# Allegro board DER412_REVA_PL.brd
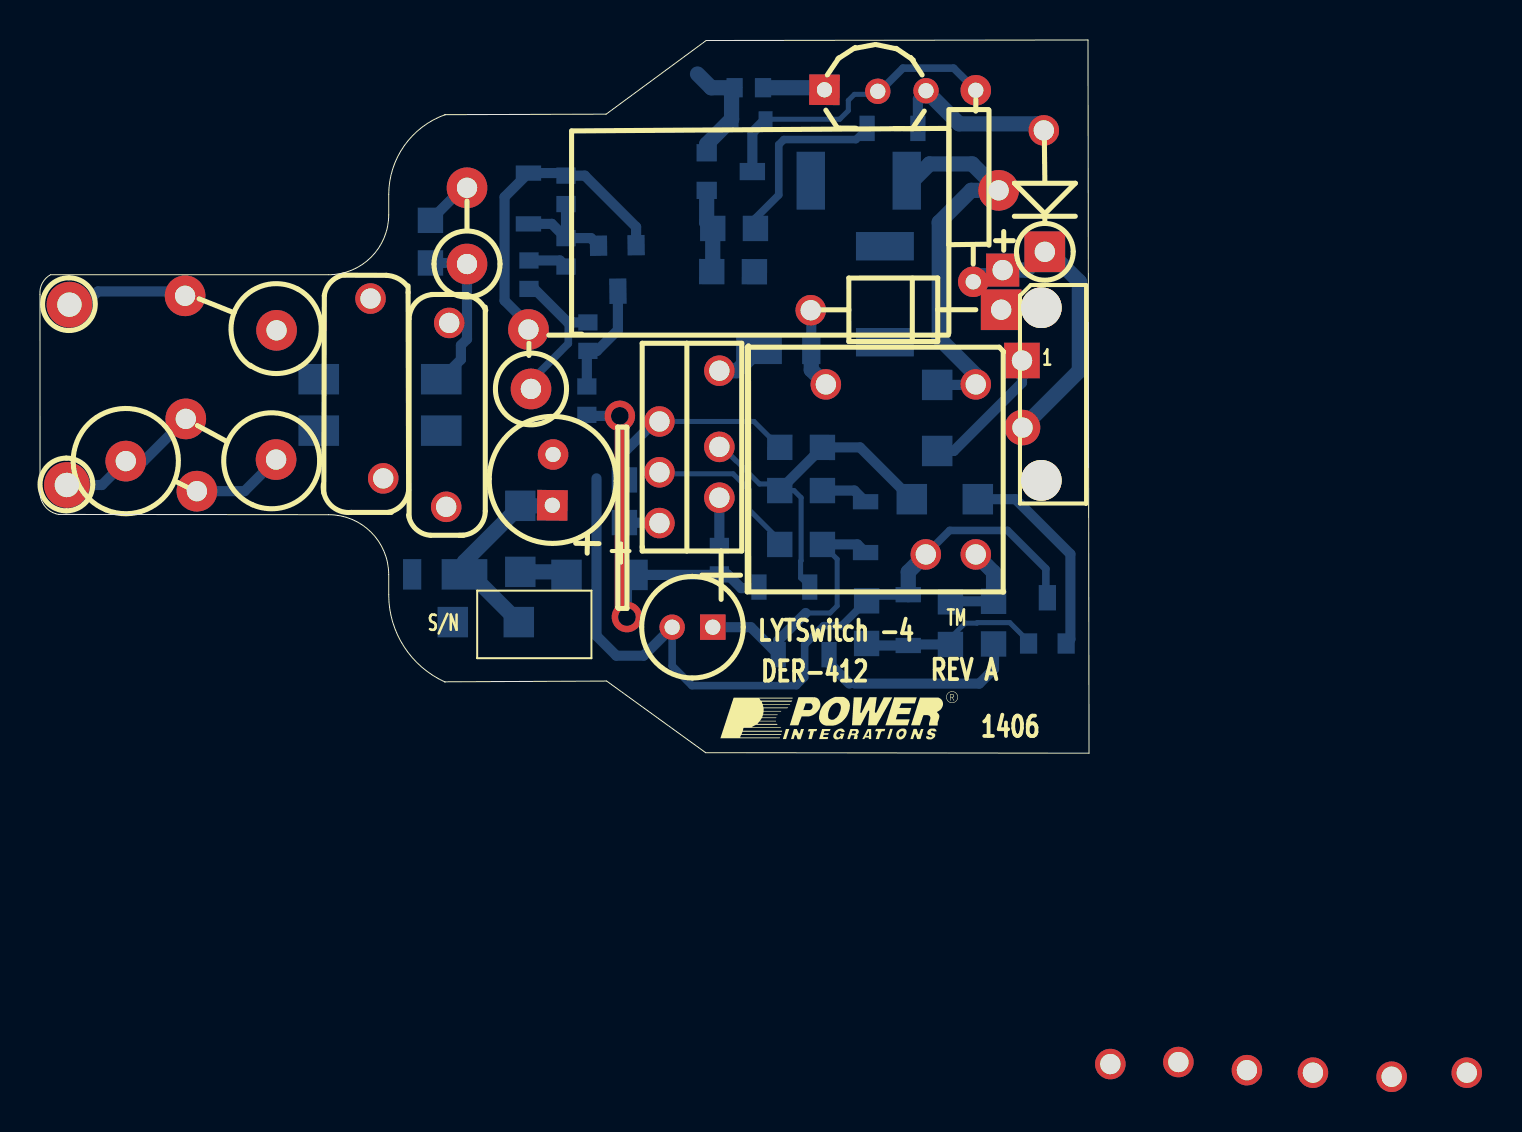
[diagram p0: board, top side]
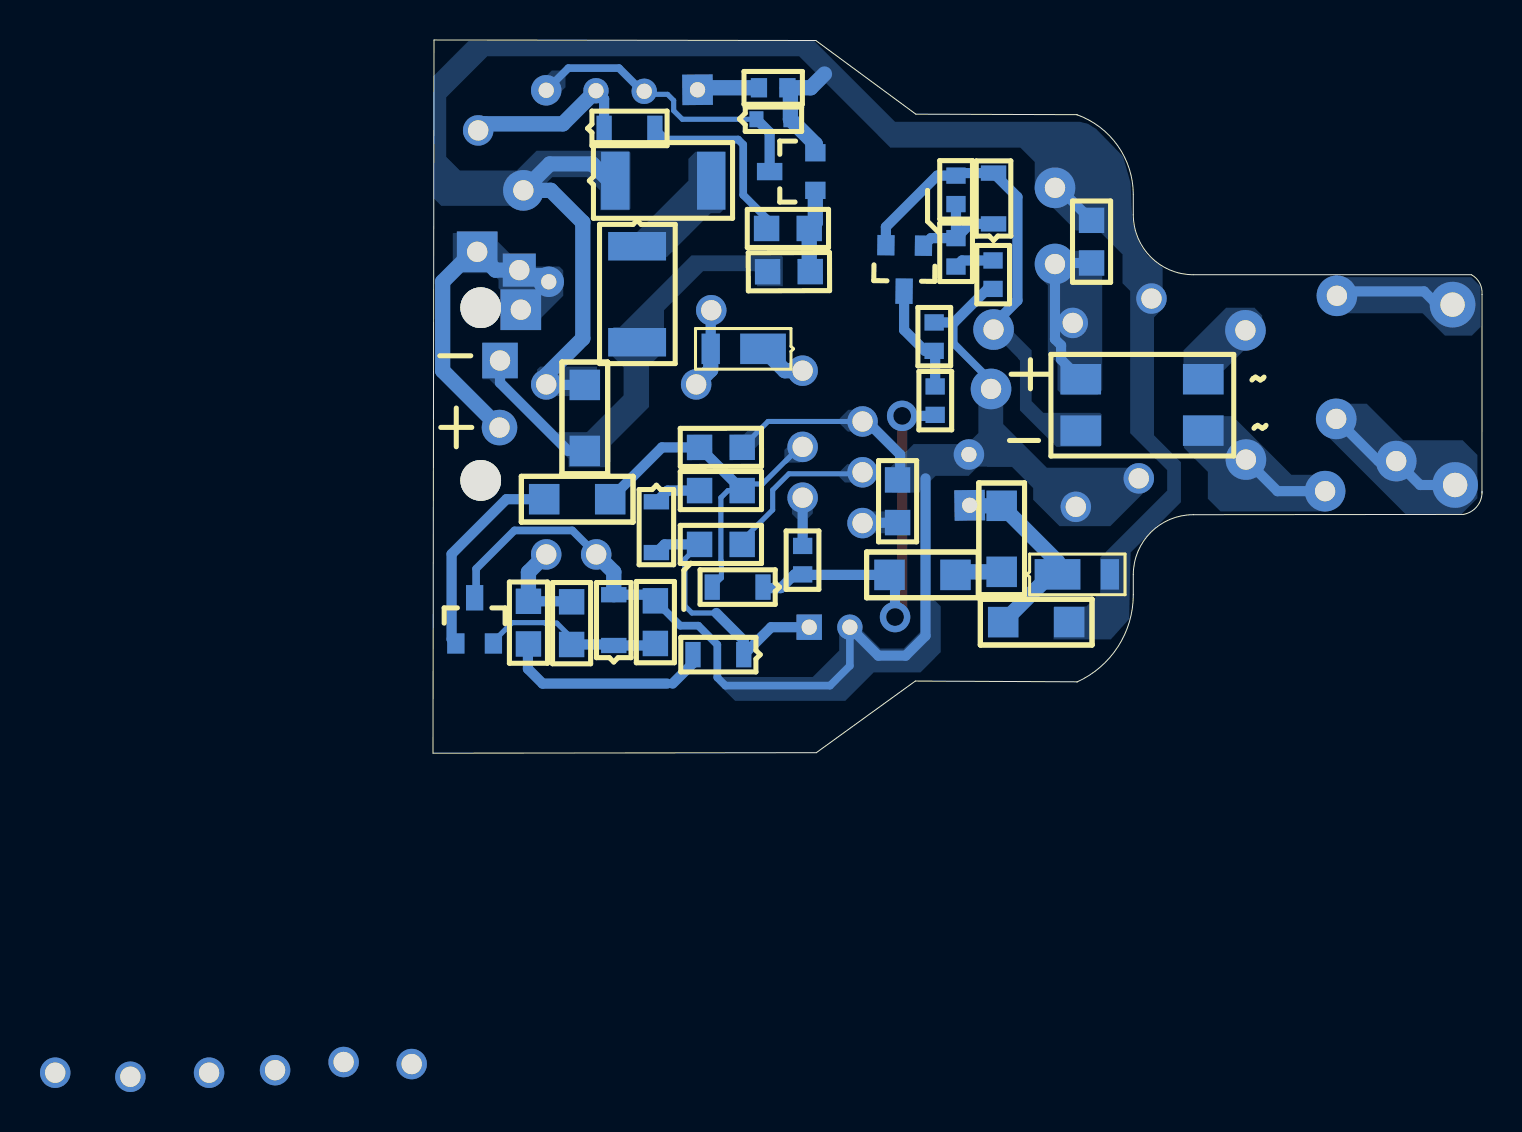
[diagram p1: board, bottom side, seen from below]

Outline 52.48 x 35.66 mm; copper layers: TOP, BOTTOM. Coordinates in mm from the lower left corner of the outline.
Outline path: 0,13 0,22.94 arc(0.12,23.51) 0.53,23.93 14.45,23.92 arc(16.57,24.8) 17.44,26.92 17.44,27.92 arc(18.22,30.37) 20.27,31.93 ; 0,13.08 arc(0.26,12.33) 0.94,11.94 14.45,11.93 arc(16.57,11.05) 17.44,8.93 17.44,7.92 arc(18.21,5.32) 20.27,3.56 ; 20.27,31.93 20.24,31.92 ; 20.27,31.93 28.32,31.95 33.32,35.64 52.43,35.66 52.48,0 33.3,0.03 28.35,3.61 20.24,3.57

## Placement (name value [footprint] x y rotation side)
BR1  B10S-G  [PISMSOIC4]  13.94 16.13 90 bottom
C1  10 nF  [PINPCAPRAD500X200400030]  20.29 21.95 270 top
C3  220 nF  [PI_NP_CAP_RAD470X220LS400D40]  16.54 23.09 270 top
C4  2.2 uF  [PIPOLCAPCYLD250LS100030]  25.63 12.4 89.1 top
C5  100 uF  [PIPOLCAPCYLD400LS200040]  48.69 23.5 90 top
C6  4.7 uF  [PIPOLCAPCLYD200LS80030]  33.66 6.3 180 top
C7  4.7 uF  [PISMC0805]  39.14 15.29 179.9 bottom
C8  680 pF  [PISMC0603]  27.41 20.12 90 bottom
C9  100 pF  [PISMC0603]  24.46 23.22 90 bottom
D2  DFLR1600-7  [PISMDDFLR120012]  21.26 8.94 0 bottom
D3  STTH1R06RL  [PIDV200X110X040DO41#2]  48.08 22.17 180 top
D4  BAV21WS-7-F  [PISMSOD323]  36.93 4.93 0 bottom
D5  DFLU1200-7  [PISMDDFLR120012]  35.94 20.22 180 bottom
D6  BAV16WS-7-F  [PISMSOD323]  41.3 12.57 270 bottom
D7  BAV16WS-7-F  [PISMSOD323]  43.43 5.38 90 bottom
D8  BAV16WS-7-F  [PISMSOD323]  24.43 26.47 90 bottom
D9  BAV16WS-7-F  [PISMSOD323]  35.97 8.31 0 bottom
D10  DL4003  [PISMDMLL4112]  43.36 28.63 180 bottom
D11  DL4003  [PISMDMLL4112]  42.27 25.35 270 bottom
FR1  47  [PI_2W_VRES240LS200D040]  11.58 20.73 151.2 top
J5  CON2  [PI_CONN_LEE_LEDS]  49.07 19.74 0 top
L  PCB Terminal 22 AWG  [PI_HOLE_22AWG]  1.47 22.43 0 top
L1  4.7 mH  [PI12WVRESD180LS150D040]  21.36 24.46 90 top
N  PCB Terminal 22 AWG  [PI_HOLE_22AWG]  1.35 13.41 0 top
NOREF  -  []  0.94 11.94 90 top
NOREF#2  -  []  -225.4 -138.86 0 top
NOREF#3  -  []  34.04 0.69 0 top
NOREF#4  -  []  -147.58 60.15 0 top
NOREF#5  -  []  0 14.02 0 top
NOREF#6  -  []  52.48 0 90 top
Q1  MMBT3904  [PISMSOT23132]  29.82 25.4 0.7 bottom
Q4  2N7000  [PITO92R100]  39.24 33.17 359.5 top
Q5  MMBT3904  [PISMSOT23132]  33.35 30.02 90 bottom
R1  10 k  [PISMR0805]  19.53 24.51 90 bottom
R6  27  [PI1WRESD200LS725D040]  24.56 18.21 90.7 top
R8  510 k  [PISMR1206]  20.65 6.55 0 bottom
R9  1.50 M  [PISMR1206]  24.03 12.37 270 bottom
R10  1.50 M  [PISMR1206]  26.34 8.92 0 bottom
R13  82 k  [PISMR0603]  27.36 16.92 90 bottom
R14  137 k  [PISMR0805]  37.01 10.44 0 bottom
R15  24.9 k  [PISMR0805]  29.24 13.67 270 bottom
R16  6.2 k  [PISMR0805]  39.14 13.13 180 bottom
R17  20  [PISMR1206]  46.91 12.7 180 bottom
R18  62 k  [PISMR0805]  45.54 5.44 90 bottom
R20  100 k  [PISMR0603]  26.31 27.46 90 bottom
R21  10 k  [PISMR0603]  26.31 24.33 90 bottom
R22  191 k  [PISMR0603]  33.99 10.36 270 bottom
R24  200  [PI2WRESD200LS725D040#2]  4.29 14.61 338 top
R25  5.1 k  [PISMR0805]  41.35 7.62 270 bottom
R33  10  [PISMR0805]  47.7 7.59 270 bottom
R35  680  [PISMR0603]  36.17 33.27 180 bottom
R36  1 M  [PI14WRESD100LS400D030]  46.69 33.73 270 top
R37  1 k  [PISMR0805]  33.6 24.08 359.8 bottom
R38  130  [PISMR1206]  44.88 18.41 270 bottom
R39  10 k  [PISMR0805]  33.66 26.24 0 bottom
R40  200  [PI2WRESD200LS725D040]  11.81 14.68 156.3 top
T1  EE13  [PI_BOBBIN_EE13V_10P]  46.81 18.44 180 top
U1  LYT4322E  [PIICESIP76TH]  30.99 11.51 90 top
U2  LM431AIM3  [PISMSOT23123]  49.45 5.49 180 bottom
VR1  DZ2S062M0L  [PI_SM_D_SSMINI2P]  36.3 31.7 180 bottom
VR2  1N4761A  [PIDV200X110X040DO41]  50.27 25.07 90 top
VR3  BZX384-B56,115  [PISMSOD323]  43.92 31.24 180 bottom

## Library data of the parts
BR1 = DIODE BRIDGE_~~+-: alternate symbols: (pi_sm_soic4_slot); room: 1
C1 C3 C7-C9 = CAP NP
C4 = CAP POL: alternate symbols: (pipolcapcyld250ls100030h)
C5 = CAP POL: alternate symbols: (pipolcapcyld400ls200040800h)
C6 = CAP POL: alternate symbols: (pipolcapclyd200ls80030h)
D2 D4-D11 = DIODE
D3 = DIODE: alternate symbols: (pidax475x125040do41,pidax390x125040do41)
FR1 = R: alternate symbols: (PI_2W_RES240LS500D040,pi_2w_resd145ls455d040); tolerance: 5%
J5 = CON2
L N = TERM_1Pin
L1 = INDUCTOR
Q1 Q5 = NPN_BEC
Q4 = FET_N_SGD
R1 = R: room: 1
R6 = R: alternate symbols: (pi1wvresd120ls200d040,pi1wvresd120ls300d040,pi1wvresd200ls200d040,pi1wvresd200ls300d040,pi1wvresd200ls350d040)
R8-R10 R13-R18 R20-R22 R25 R33 R35 R37-R39 = R
R24 R40 = R: alternate symbols: (pi2wresd200ls900d040,pi2wvresd200ls300d040,pi2wvresd200ls400d040,pi2wresd200ls725d040)
R36 = R: alternate symbols: (pi14wvresd100ls200d030,pi14wresd100ls400d030,pi14wresd100ls500d030)
T1 = BEE13/10PINS/GENERIC
U1 = LNK40X_eSIP
U2 = TL431/SOT-23_CAR
VR1 VR3 = DIODE_ZENER
VR2 = DIODE_ZENER: alternate symbols: (pidax475x125040do41,pidv200x110x040do41wbead,pidax390x125040do41)

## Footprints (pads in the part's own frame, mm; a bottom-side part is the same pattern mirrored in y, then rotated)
PI1WRESD200LS725D040
  round 2.032 hole 1.016: 1(0,0) 2(2.973,0.09)
PI2WRESD200LS725D040
  round 2.032 hole 1.016: 1(0,0) 2(4.953,-0.051)
PI2WRESD200LS725D040#2
  round 2.032 hole 1.016: 1(0,0) 2(3.862,-0.059)
PI12WVRESD180LS150D040
  round 2.032 hole 1.016: 1(0,0) 2(3.81,0)
PI14WRESD100LS400D030
  round 1.524 hole 0.762: 1(0.584,0.127) 2(10.16,0)
PI_2W_VRES240LS200D040
  round 2.032 hole 1.016: 1(-0.02,-0.488) 2(4.822,0.207)
PI_BOBBIN_EE13V_10P
  round 1.524 hole 1.016: 1(0,0) 2(-16.866,34.417) 3(-20.803,34.62) 4(7.501,0) 5(-24.562,34.417) 6(-6.731,33.985) 7(-10.135,33.884) 8(-13.564,34.29) 9(2.499,8.501) 10(0,8.501)
PI_CONN_LEE_LEDS
  round 2.032 hole 2.032: (1.016,2.54) (1.016,-6.096)
  rect 1.778x1.778 hole 1.016: 1(0.051,-0.102)
  round 1.778 hole 1.016: 2(0.076,-3.454)
PI_HOLE_22AWG
  round 2.286 hole 1.219: 1(0,0)
PI_NP_CAP_RAD470X220LS400D40
  round 1.524 hole 1.016: 1(0.356,0) 2(9.347,0.635)
PI_SM_D_SSMINI2P
  rect 0.699x0.8 smd: 1(0,0) 2(1.7,0)
PIDV200X110X040DO41
  rect 2.032x2.032 hole 1.016: 1(0,0)
  round 1.524 hole 1.016: 2(6.071,0.051)
PIDV200X110X040DO41#2
  rect 2.032x2.032 hole 1.016: 1(0,0)
  round 1.524 hole 1.016: 2(9.525,0.022)
PIICESIP76TH
  round 1.524 hole 1.016: 1(0,0) 2(1.27,-2.997) 3(2.54,0) 4(3.81,-2.997) 5(5.08,0) 7(7.62,-2.997)
PINPCAPRAD500X200400030
  round 1.524 hole 1.016: 1(0.432,0.178) 2(9.627,0.025)
PIPOLCAPCLYD200LS80030
  rect 1.27x1.27 hole 0.762: 1(0,0)
  round 1.27 hole 0.762: 2(2.032,0)
PIPOLCAPCYLD250LS100030
  rect 1.524x1.524 hole 0.762: 1(0,0)
  round 1.524 hole 0.762: 2(2.54,0)
PIPOLCAPCYLD400LS200040
  rect 1.651x1.651 hole 1.016: 1(0.66,0.533)
  round 2.032 hole 1.016: 2(4.648,0.737)
PISMC0603
  rect 0.813x0.965 smd: 1(0,0) 2(1.422,0)
PISMC0805
  rect 1.27x1.27 smd: 1(0,0) 2(2.134,0)
PISMDDFLR120012
  rect 2.286x1.524 smd: 1(-0.025,0)
  rect 0.914x1.524 smd: 2(-2.642,0)
PISMDMLL4112
  rect 1.422x2.896 smd: 1(0,0) 2(4.801,0)
PISMR0603
  rect 0.813x0.965 smd: 1(0,0) 2(1.422,0)
PISMR0805
  rect 1.27x1.27 smd: 1(0,0) 2(2.134,0)
PISMR1206
  rect 1.524x1.524 smd: 1(0,0) 2(3.302,0)
PISMSOD323
  rect 0.762x1.27 smd: 1(0,0) 2(2.54,0)
PISMSOIC4
  rect 1.524x2.032 smd: 1(0,0) 2(2.57,0) 3(2.57,6.129) 4(0,6.129)
PISMSOT23123
  rect 0.864x1.016 smd: 1(-1.88,0) 3(0,0)
  rect 0.864x1.27 smd: 2(-0.94,2.286)
PISMSOT23132
  rect 0.864x1.016 smd: 1(-1.88,0) 2(0,0)
  rect 0.864x1.27 smd: 3(-0.94,2.286)
PITO92R100
  rect 1.524x1.524 hole 0.762: 1(0,0)
  round 1.27 hole 0.762: 2(2.667,-0.051) 3(5.08,0)

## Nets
N1678526: C1.2 C3.2 C4.2 C6.2 C7.2 C8.2 C9.1 D7.2 R6.1 R15.1 R25.1 T1.9 U1.5(S) U2.2(A)
N2200496: C4.1 D2.1 R8.2 R9.1
N2229506: BR1.4 D8.2 Q1.2(EMITTER) R6.2 R20.2
N2302506: FR1.2 L.1
N2491459: C7.1 D9.2 R16.2 R17.2 U1.4(BP)
N2492720: D5.1 U1.7(D)
N2492766: R15.2 U1.1(R)
N2493445: C3.1 C5.2 D2.2 D10.1 L1.2 Q5.2(EMITTER) R1.2 R8.1 R35.2 R38.1 T1.1 VR1.2
N2532048: R14.1 U1.3(FB)
N2536376: BR1.1 R24.2 R40.1
N2538393: BR1.3 C1.1 L1.1 R1.1
N3672068: C5.1 D3.1 J5.2 R36.2 VR2.1
N3711440: D3.2 D5.2 T1.4
N3740281: R22.1 U1.2(V)
N3830550: C6.1 D4.1 D6.2 R14.2
N3837669: R9.2 R10.1
N3895372: C8.1 Q1.3(COLLECTOR) R13.2
N3895502: D8.1 Q1.1(BASE) R20.1 R21.2
N3896990: D9.1 R10.2 R13.1 R22.2
N3918631: D7.1 R18.1 R25.2 U2.3(VREF)
N3918661: R17.1 U2.1(C)
N3918954: R18.2 R33.1 T1.10
N3939020: D6.1 R16.1
N3945438: T1.3
N3949879: D4.2 R33.2
N3952070: BR1.2 FR1.1
N3964753: Q4.2(G) Q5.3(COLLECTOR) R36.1 VR1.1
N3964758: Q4.1(S) R35.1
N3964791: Q4.3(D) VR2.2 VR3.1
N3965046: D11.2 J5.1 R37.2 R38.2
N3965058: Q5.1(BASE) R37.1 R39.1
N3965494: R39.2 VR3.2
N3967550: N.1 R24.1 R40.2
N38954281: C9.2 R21.1
N39661570: D10.2 D11.1

Pads without a net: T1 2 5 6 7 8

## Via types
v1: diameter 1.524, hole 0.889, TOP to BOTTOM, 2 vias

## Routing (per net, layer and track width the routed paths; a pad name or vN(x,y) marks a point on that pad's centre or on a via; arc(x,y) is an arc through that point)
N1678526: length 59.4
  BOTTOM w0.254: C7.2 35.72,16.59 U1.5
  BOTTOM w0.381: 26.41,21.54 26.43,21.52 26.43,20.49 24.56,18.62 R6.1 ; R25.1 40.11,6.38 39.2,6.38 38.25,5.42 38.25,3.78 37.85,3.38 32.61,3.38 31.62,4.37 C6.2 ; R15.1 28.93,13.64 ; U2.2 50.32,7.85 50.32,9.22 48.4,11.14 45.5,11.14 44.31,9.95 T1.9
  BOTTOM w0.508: D7.2 41.66,7.92 R25.1 ; C8.2 26.41,21.54 24.73,23.22 C9.1 ; U1.5 30.76,16.59 29.11,14.94 29.11,13.67 R15.1 ; C6.2 30.2,4.88 28.83,4.88 27.84,5.87 27.84,13.74
  BOTTOM w0.762: T1.9 43.43,9.06 D7.2
N2200496: length 9.9
  BOTTOM w0.762: R8.2 21.56,8.94 D2.1 21.23,9.58 R9.1 25.6,12.37 C4.1
N2229506: length 16.3
  BOTTOM w0.508: Q1.2 29.82,26.31 27.25,28.88 R20.2 26.19,29.01 D8.2 23.24,27.81 23.24,22.63 24.64,21.23
N2302506: length 6.1
  BOTTOM w0.508: L.1 2.24,22.43 2.9,23.09 7.04,23.09 FR1.2
N2491459: length 19.4
  BOTTOM w0.254: 34.11,15.32 34.82,14.61 ; 34.11,15.32 34.14,15.32 35.99,13.46 36.68,13.46 R16.2 37.72,13.13 38.07,12.78 38.07,9.63 38.05,9.6 38.05,8.76 D9.2 ; 34.11,15.32 U1.4
  BOTTOM w0.508: R17.2 41.02,15.29 C7.1 37.01,13.16 R16.2
N2492720: length 2.4
  BOTTOM w0.762: D5.1 34.87,19.13 U1.7
N2492766: length 1.8
  BOTTOM w0.508: R15.2 U1.1
N2493445: length 29.2
  BOTTOM w0.508: R1.2 21.16,28.27 L1.2 ; T1.1 46.79,18.41 R38.1
  BOTTOM w0.762: D10.1 43.66,28.63 44.5,29.46 46.63,29.46 C5.2 ; 47.8,27.99 C5.2 ; C5.2 46.58,28.14 44.98,26.54 44.98,20.74 46.81,18.91 T1.1 ; C5.2 47.96,28.68 ; Q5.2 33.35,30.45 VR1.2 34.6,33.12 R35.2 33.58,33.27 32.89,33.96
N2532048: length 8.3
  BOTTOM w0.254: 30.99,14.17 U1.3 31.06,13.97 34.67,13.97 35.48,13.16 35.48,12.17 37.01,10.64 R14.1
N2536376: length 4.6
  BOTTOM w0.508: R40.1 10.23,13.1 R24.2
N2538393: length 8.1
  BOTTOM w0.508: BR1.3 21.06,19.68 21.06,20.4 21.36,20.7 L1.1 21.31,24.51 R1.1
N3672068: length 16.2
  BOTTOM w0.508: 47.88,23.88 47.75,23.75 47.06,23.75 46.93,23.62 46.75,23.62
  BOTTOM w0.762: J5.2 51.99,19.13 51.99,23.57 50.5,25.07 VR2.1 49.35,24.16 C5.1 47.88,23.88 47.01,23.88 46.75,23.62
N3711440: length 4
  BOTTOM w0.508: D5.2 38.58,22.12 D3.2
  BOTTOM w0.762: D5.2 38.58,19.17 T1.4
N3740281: length 2.4
  BOTTOM w0.508: R22.1 U1.2
N3830550: length 13.9
  BOTTOM w0.254: 38.3,7.01 39.52,7.01 39.88,7.37 39.88,9.7 R14.2
  BOTTOM w0.508: 38.3,7.01 36.93,5.64 D4.1 35.56,6.3 C6.1 ; 41.3,10.03 40.89,10.44 R14.2
N3837669: length 2.4
  BOTTOM w0.762: R10.1 26.19,9.07 R9.2
N3895372: length 5.7
  BOTTOM w0.508: R13.2 27.36,20.07 C8.1 27.86,20.12 28.91,21.16 Q1.3
N3895502: length 5.7
  BOTTOM w0.508: R20.1 R21.2 ; R21.2 25.6,26.47 D8.1 ; R21.2 27.56,25.76 Q1.1
N3896990: length 20.7
  TOP w0.508: v1(29.36,6.81) 29.01,7.16 v1(29.01,16.87)
  BOTTOM w0.508: v1(29.01,16.87) 27.41,16.87 R13.1 ; v1(29.36,6.81) 29.36,8.64 R10.2 33.96,8.92 R22.2 34.39,8.94 35.08,8.26 35.92,8.26 D9.1
N3918631: length 9.3
  BOTTOM w0.254: R18.1 45.54,5.77 46.28,6.5 46.86,6.5 46.89,6.53 48.52,6.53 49.45,5.59 U2.3
  BOTTOM w0.508: R25.2 41.45,5.38 D7.1 43.48,5.44 R18.1
N3918661: length 10.3
  BOTTOM w0.508: U2.1 51.54,5.7 51.54,9.96 48.8,12.7 R17.1
N3918954: length 4.9
  BOTTOM w0.508: R18.2 45.57,7.59 R33.1
  BOTTOM w0.762: R33.1 47.7,9.05 T1.10
N3939020: length 2.4
  BOTTOM w0.508: D6.1 40.74,13.13 R16.1
N3949879: length 10.7
  BOTTOM w0.254: 40.49,3.48 40.77,3.48
  BOTTOM w0.508: 40.49,3.48 39.47,4.5 D4.2 ; R33.2 47.73,5.44 47.73,4.22 46.99,3.48 40.77,3.48
N3964753: length 15.2
  BOTTOM w0.254: Q4.2 41.76,32.94 40.74,32.94 40.44,32.64 40.44,32.13 40,31.7 VR1.1
  BOTTOM w0.381: R36.1 45.7,34.25 43.17,34.25 42.01,33.1 Q4.2
  BOTTOM w0.508: VR1.1 35.64,31.04 Q5.3
N3964758: length 3.1
  BOTTOM w0.762: Q4.1 39.14,33.27 R35.1
N3964791: length 8.8
  BOTTOM w0.508: VR3.1 43.92,32.72 Q4.3
  BOTTOM w0.762: Q4.3 45.98,31.47 49.89,31.47 VR2.2
N3965046: length 6.8
  BOTTOM w0.508: R38.2 45.71,15.11 49.12,18.52 J5.1
N3965058: length 4.2
  BOTTOM w0.762: Q5.1 33.35,26.54 R39.1 33.66,24.13 R37.1
N3965494: length 9.4
  BOTTOM w0.381: R39.2 35.79,26.75 36.96,27.91 36.96,30.43 37.21,30.68 40.82,30.68 VR3.2
N3967550: length 7.3
  BOTTOM w0.508: R40.2 5.18,14.61 R24.1 3.1,13.41 N.1
N38954281: length 2
  BOTTOM w0.508: C9.2 26.01,24.64 R21.1

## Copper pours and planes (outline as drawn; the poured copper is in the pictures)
N1678526 on BOTTOM: 18.59,11.35 16.51,13.44 16.51,14.1 16.69,14.27 21.77,14.27 23.95,16.46 23.95,18.72 24.03,18.8 25.2,18.8 25.2,16 25.74,15.46 28.44,15.46 29.62,14.27 29.62,13.13 29.51,13.03 28.17,13.03 27.33,13.87 25.68,13.87 25.22,14.33 24.76,14.33 24.75,14.31 23.51,14.31 22.45,13.26 22.45,12.67 21.13,11.35
N1678526 on BOTTOM: 30.73,17.17 31.7,17.17 32.13,16.74 32.13,16.48 31.72,16.08 30.78,16.08 30.58,16.28 30.58,17.02
N1678526 on BOTTOM: 36.19,16.21 36.65,16.21 37.41,15.44 37.41,15.14 37.19,14.91 36.7,14.91 36.09,15.52 36.09,16.1
N1678526 on BOTTOM: 27.66,7.92 27.84,7.92 28.09,7.67 28.09,6.12 28.07,6.1 28.93,5.23 30.1,5.23 31.39,6.53 31.39,6.58 31.85,6.58 32.16,6.27 32.16,5.13 33.48,3.81 38.05,3.81 38.25,3.61 38.25,3.51 37.36,2.62 31.85,2.62 30.43,4.04 28.09,4.04 27.08,5.05 27.08,7.34
N2229506 on BOTTOM: 24.08,21.69 24.71,21.69 25.15,21.26 24.33,20.45 23.9,20.45 23.22,19.76 23.22,19.74 23.11,19.63 23.11,17.14 21.29,15.32 19.13,15.32 19.02,15.42 19.02,16.94 19.1,17.02 21.95,17.02 22.53,17.6 22.53,20.14
N2302506 on BOTTOM: 0.53,23.8 7.65,23.8 8.13,23.32 8.13,22.33 7.8,22 2.97,22 1.85,20.88 0.51,20.88 0.08,21.31 0.08,23.34
N2491459 on BOTTOM: 34.37,15.65 34.42,15.65 34.9,15.16 34.9,14.71 34.72,14.53 34.11,14.53 33.6,15.04 33.6,15.47 33.86,15.72 34.29,15.72
N2492766 on BOTTOM: 31.22,12.09 31.52,11.79 31.52,11.25 31.27,11 29.06,11 28.8,11.25 28.8,11.94 28.96,12.09
N2493445 on BOTTOM: 44.27,19.33 47.12,19.33 47.27,19.18 47.27,17.98 47.14,17.86 44.45,17.86 44.27,18.03
N2493445 on BOTTOM: 42.7,30.12 47.29,30.12 48.72,28.7 48.72,27.43 47.47,27.43 47.04,27.86 47.04,28.27 46.51,28.8 44.78,28.8 44.15,28.17 44.12,28.17 44.12,27.18 44.15,27.15 42.67,27.15 42.6,27.23 42.6,30.02
N2493445 on BOTTOM: 18.57,5.69 17.65,6.71 17.58,10.03 15.06,12.55 15.06,14.55 16.41,15.9 16.41,21.79 15.98,22.23 15.98,24.28 16.71,24.87 17.04,25.32 17.17,25.6 17.32,25.98 17.34,26.05 17.35,26.09 17.48,26.64 17.53,27.25 17.58,28.5 17.96,29.84 19.3,31.22 19.71,31.47 20.12,31.57 29.36,31.57 33.4,35.61 50.7,35.61 52.45,33.86 52.45,27.76 52.06,27.37 47.59,27.37 47.4,27.56 47.4,28.68 47.85,29.13 51.13,29.13 51.82,29.82 51.82,32.79 49.76,34.85 34.16,34.85 29.62,30.3 29.62,30.28 23.09,30.28 22.38,29.57 22.38,28.19 20.32,26.14 19.15,26.14 19.15,26.11 17.98,24.94 17.98,23.5 17.6,23.11 17.6,16 15.75,14.15 15.75,13.13 19.1,9.78 19.1,8.05 19.09,8.04 19.79,7.34 21.39,7.34 21.44,7.29 21.44,5.69
N2532048 on BOTTOM: 31.19,14.45 31.75,14.45 32.16,14.05 32.16,13.82 31.88,13.54 30.86,13.54 30.63,13.77 30.63,14.22 30.89,14.48 31.17,14.48
N2536376 on BOTTOM: 14.91,16.85 14.91,15.27 13.72,14.07 13.72,12.7 13.69,12.7 13.08,12.09 7.8,12.09 7.26,12.62 7.26,13.92 9.54,13.92 12.47,16.85
N2538393 on BOTTOM: 21.72,25.12 22.07,24.77 22.07,23.75 21.72,23.39 21.72,19.99 21.23,19.51 21.23,18.16 20.98,17.91 19.25,17.91 19,18.16 19,25.12
N3672068 on BOTTOM: 47.6,24.97 48.62,24.97 49.25,25.6 49.25,26.01 51.46,26.01 51.49,25.98 51.49,24.16 51.33,24 49.53,24 49.2,23.67 49.2,21.26 47.57,21.26 45.96,22.87 45.96,24.14 46.15,24.33 47.35,24.33 47.62,24.61 47.62,24.94
N3740281 on BOTTOM: 33.76,13.11 34.26,13.11 34.52,12.85 34.52,11.96 34.26,11.71 33.76,11.71 33.48,11.99 33.48,12.83
N3952070 on BOTTOM: 11.38,22.28 12.8,22.28 14.94,20.14 14.94,17.98 12.93,17.98 12.93,19.02 12.98,19.08 11.71,20.35 11.38,20.35 11,20.73 11,21.89
N3964753 on BOTTOM: 46.08,34.14 46.53,34.14 47.29,33.38 47.29,32.82 46.99,32.51 46.63,32.51 45.85,33.3 45.85,33.91
N3965046 on BOTTOM: 43.87,14.3 43.59,14.58 43.59,15.39 41.67,17.31 41.67,19.37 41.12,19.91 40.92,19.91 40.92,22.15 38.96,24.1 36.4,24.1 36.27,23.98 36.27,23.37 36.25,23.34 34.98,23.34 34.98,24.82 35.05,24.89 39.55,24.89 43.13,21.31 43.46,21.31 43.46,19.81 42.94,19.29 42.94,17.89 44.78,16.05 46.28,16.05 48.87,18.64 48.87,20.19 48.79,20.27 49.86,20.27 49.99,20.14 49.99,18.69 49.66,18.69 45.69,14.73 45.69,14.33 45.67,14.3
N3967550 on BOTTOM: 7.67,17.48 8.1,17.04 8.1,16.23 3.84,11.96 1.02,11.96 0.23,12.75 0.23,14.91 0.97,15.65 3.94,15.65 5.77,17.48
N39661570 on BOTTOM: 37.92,30.07 39.34,30.07 39.7,29.72 39.7,28.63 42.37,25.96 43.15,25.96 43.21,25.91 43.21,24.82 40.77,24.82 38.58,27 38.13,27 37.9,27.23 37.9,30.05

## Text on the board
Ref Des/Silkscreen Bottom: + | -
Ref Des/Silkscreen Top: S/N | TM | LYTSwitch -4 | DER-412 | REV A | 1406
PEN17: PLEASE DELETE THESE PINS | SLOT | 13   MATERIAL FR4 COPPER 2oz THICKNESS 0.031"
User.5: FIGURE | SIZE | 30.0 | 35.0 | 40.0 | 48.0 | 80.0 | DRILL CHART: TOP to BOTTOM | ALL UNITS ARE IN MILS | QTY | 11 | 2 | 36
